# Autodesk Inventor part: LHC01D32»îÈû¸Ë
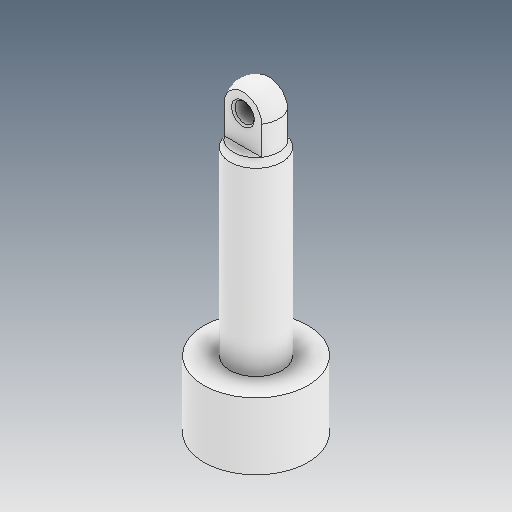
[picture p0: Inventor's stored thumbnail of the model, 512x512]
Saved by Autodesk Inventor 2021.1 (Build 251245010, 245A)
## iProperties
Created: 2021-06
Part Number: LHC01D32»îÈû¸Ë
Material: Ogólny
Document SubType Name: Modeling
Designer: user
Density: 1 g/cm^3
Appearance: Domyślna
Author: user
Revision Number: ÈÎºÎ
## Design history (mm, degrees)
feature "ÊäÈë1"
node "Bryła1"
